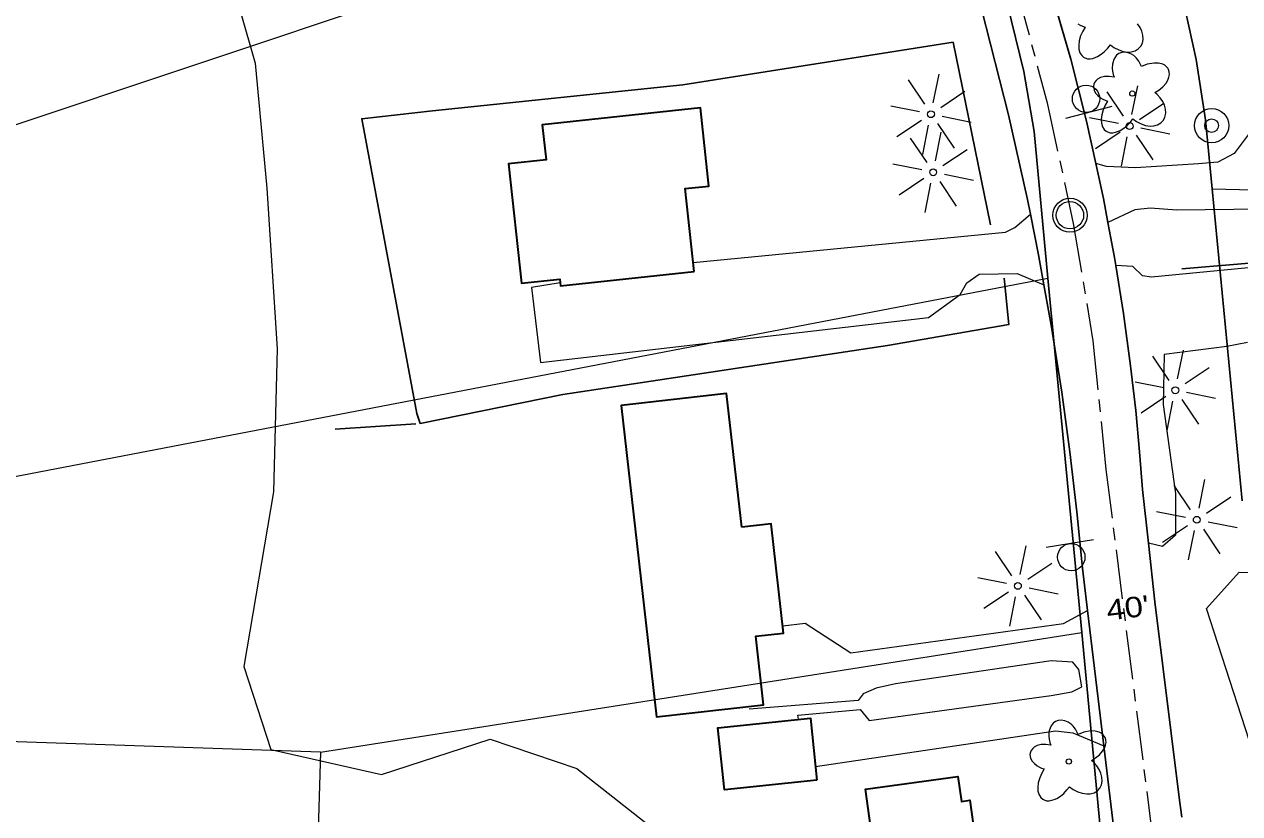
# Model space of a CAD drawing. Extents: x -861682 to -858969, y -1797841 to -1795153.
# Drawn here: x -859508.8 to -859153.4, y -1796143 to -1795912 of the extents above; entities that cross this region are included whole.
import ezdxf

# ---------------------------------------------------------------- set-up
doc = ezdxf.new("R2010")
doc.units = 0
doc.header["$LTSCALE"] = 2.4
doc.linetypes.add('LONG_DASH_SHORT_DASH', pattern=[9.9, 6, -1.2, 1.5, -1.2])
for name, color, linetype, lineweight in [('10', 7, 'Continuous', 25), ('11', 7, 'Continuous', 13), ('12', 7, 'Continuous', 35), ('14', 7, 'Continuous', 25), ('17', 7, 'Continuous', 13), ('18', 7, 'Continuous', 13), ('21', 7, 'Continuous', 13), ('30', 7, 'Continuous', 13), ('31', 7, 'Continuous', 13), ('32', 7, 'LONG_DASH_SHORT_DASH', 13), ('36', 7, 'Continuous', 13), ('42', 7, 'Continuous', 25)]:
    doc.layers.add(name, color=color, linetype=linetype, lineweight=lineweight)
doc.layers.add('43', color=7, linetype='Continuous')

msp = doc.modelspace()

# ---------------------------------------------------------------- linework, layer by layer
at = {"layer": '10'}
for p, q in [((-859180.121, -1796063.829), (-859181.863, -1796048.128)), ((-859197.871, -1796083.551), (-859199.352, -1796071.145)), ((-859197.871, -1796083.551), (-859193.138, -1796123.219))]:
    msp.add_line(p, q, dxfattribs=at)
for points in [[(-859195.488, -1795952.759), (-859198.204, -1795940.389), (-859202.803, -1795922.229), (-859208.876, -1795901.043), (-859216.374, -1795877.989), (-859222.374, -1795861.368), (-859224.152, -1795856.696)], [(-859214.603, -1795967.597), (-859215.462, -1795963.305), (-859220.98, -1795938.568), (-859228.914, -1795907.477), (-859230.246, -1795902.657)], [(-859195.488, -1795952.759), (-859193.242, -1795962.991), (-859191.918, -1795970.065)], [(-859210.647, -1795988.294), (-859212.222, -1795979.514), (-859214.603, -1795967.597)], [(-859191.918, -1795970.065), (-859189.999, -1795980.322), (-859189.628, -1795982.635)], [(-859189.628, -1795982.635), (-859187.383, -1795996.643), (-859185.313, -1796011.931), (-859183.826, -1796025.071), (-859182.696, -1796037.14), (-859181.863, -1796048.128)], [(-859210.647, -1795988.294), (-859208.526, -1796000.123), (-859205.447, -1796019.718), (-859203.055, -1796037.187), (-859200.99, -1796054.697), (-859199.352, -1796071.145)], [(-859180.121, -1796063.829), (-859178.218, -1796080.987), (-859171.015, -1796139.046), (-859170.355, -1796144.002)], [(-859193.138, -1796123.219), (-859185.092, -1796190.648), (-859181.823, -1796229.868)]]:
    msp.add_lwpolyline(points, dxfattribs=at)
at = {"layer": '11'}
for points in [[(-859138.966, -1795909.721), (-859146.102, -1795933.276), (-859149.733, -1795942.803), (-859155.018, -1795949.883), (-859159.831, -1795952.351), (-859165.413, -1795952.878), (-859183.893, -1795954.081), (-859192.373, -1795953.671), (-859195.488, -1795952.759)], [(-859127.758, -1795912.644), (-859137.418, -1795947.471), (-859137.261, -1795952.153), (-859134.574, -1795954.343), (-859128.865, -1795954.666), (-859114.589, -1795953.858), (-859113.648, -1795965.788), (-859171.8, -1795966.396), (-859179.569, -1795965.851), (-859184.024, -1795966.336), (-859191.918, -1795970.065)], [(-859313.252, -1795981.692), (-859221.93, -1795972.849), (-859219.15, -1795971.531), (-859214.603, -1795967.597)], [(-859042.087, -1795984.119), (-859043.027, -1795974.565), (-859116.563, -1795980.029), (-859179.237, -1795986.038), (-859181.848, -1795985.61), (-859184.682, -1795982.919), (-859189.628, -1795982.635)], [(-859352.064, -1795987.667), (-859360.515, -1795989.037), (-859357.825, -1796011.045), (-859244.428, -1795997.858), (-859235.189, -1795991.073), (-859233.172, -1795987.708), (-859229.548, -1795985.138), (-859218.502, -1795984.92), (-859210.647, -1795988.294)], [(-859151.173, -1796005.109), (-859157.125, -1796006.335), (-859175.528, -1796008.666), (-859175.793, -1796023.268), (-859172.173, -1796049.334), (-859172.198, -1796061.561), (-859176.002, -1796064.824), (-859180.121, -1796063.829)], [(-859286.997, -1796088.033), (-859280.413, -1796087.241), (-859267.136, -1796096.004), (-859204.945, -1796087.367), (-859197.871, -1796083.551)], [(-859282.365, -1796115.409), (-859282.571, -1796114.174), (-859264.417, -1796112.532), (-859261.719, -1796115.776), (-859208.529, -1796108.457), (-859202.495, -1796107.393), (-859199.532, -1796105.945), (-859200.435, -1796100.799), (-859202.213, -1796098.695), (-859208.514, -1796098.268), (-859254.084, -1796105.035), (-859259.709, -1796106.333), (-859263.455, -1796107.948), (-859265.008, -1796109.933), (-859296.879, -1796112.451)], [(-859277.429, -1796129.188), (-859207.286, -1796118.788), (-859202.224, -1796119.356), (-859193.138, -1796123.219)]]:
    msp.add_lwpolyline(points, dxfattribs=at)
at = {"layer": '12'}
for points in [[(-859312.961, -1795984.369), (-859315.594, -1795960.115), (-859308.609, -1795959.357), (-859311.092, -1795936.477), (-859357.336, -1795941.495), (-859356.229, -1795951.701), (-859367.188, -1795952.89), (-859363.402, -1795987.785), (-859352.183, -1795986.568), (-859351.962, -1795988.603)], [(-859298.957, -1796059.197), (-859303.418, -1796020.082), (-859334.276, -1796023.601), (-859323.886, -1796114.708), (-859292.647, -1796111.145), (-859294.931, -1796091.119), (-859286.751, -1796090.186), (-859290.397, -1796058.221)], [(-859277.003, -1796133.174), (-859304.082, -1796136.068), (-859306.02, -1796117.937), (-859278.941, -1796115.043)], [(-859256.929, -1796178.303), (-859262.819, -1796135.875), (-859235.792, -1796132.123), (-859234.778, -1796139.424), (-859232.291, -1796139.079), (-859227.418, -1796174.209)]]:
    msp.add_lwpolyline(points, close=True, dxfattribs=at)
at = {"layer": '14'}
msp.add_line((-859394.281, -1796028.926), (-859417.84, -1796030.473), dxfattribs=at)
for points in [[(-859226.25, -1795970.736), (-859237.209, -1795917.304), (-859316.269, -1795929.729), (-859389.434, -1795937.322), (-859410.087, -1795939.667), (-859394.026, -1796025.89), (-859392.998, -1796028.829), (-859351.303, -1796020.368), (-859256.426, -1796005.992), (-859220.871, -1795999.853), (-859222.285, -1795986.35)], [(-859170.328, -1795983.616), (-859043.88, -1795972.952), (-859021.656, -1795971.399), (-859008.81, -1795958.001), (-858992.126, -1795956.088)]]:
    msp.add_lwpolyline(points, dxfattribs=at)
at = {"layer": '17'}
for p, q in [((-859245.489, -1795935.445), (-859250.279, -1795928.317)), ((-859243.029, -1795934.985), (-859241.303, -1795926.585)), ((-859184.936, -1795938.452), (-859183.21, -1795930.052)), ((-859240.829, -1795936.385), (-859233.733, -1795931.645)), ((-859187.396, -1795938.912), (-859192.186, -1795931.784)), ((-859246.989, -1795937.645), (-859255.451, -1795935.971)), ((-859182.736, -1795939.852), (-859175.64, -1795935.112)), ((-859246.449, -1795940.145), (-859253.675, -1795945.001)), ((-859240.389, -1795938.905), (-859231.909, -1795940.629)), ((-859188.896, -1795941.112), (-859197.358, -1795939.438)), ((-859246.069, -1795950.105), (-859244.389, -1795941.505)), ((-859242.375, -1795951.993), (-859240.649, -1795943.593)), ((-859241.729, -1795941.045), (-859236.929, -1795948.259)), ((-859188.356, -1795943.612), (-859195.582, -1795948.468)), ((-859182.296, -1795942.372), (-859173.816, -1795944.096)), ((-859244.835, -1795952.453), (-859249.625, -1795945.325)), ((-859187.976, -1795953.572), (-859186.296, -1795944.972)), ((-859183.636, -1795944.512), (-859178.836, -1795951.726)), ((-859240.175, -1795953.393), (-859233.079, -1795948.653)), ((-859246.335, -1795954.653), (-859254.797, -1795952.979)), ((-859245.795, -1795957.153), (-859253.021, -1795962.009)), ((-859245.415, -1795967.113), (-859243.735, -1795958.513)), ((-859241.075, -1795958.053), (-859236.275, -1795965.267)), ((-859239.735, -1795955.913), (-859231.255, -1795957.637)), ((-859171.586, -1796015.784), (-859169.86, -1796007.384)), ((-859174.046, -1796016.244), (-859178.836, -1796009.116)), ((-859169.386, -1796017.184), (-859162.29, -1796012.444)), ((-859175.546, -1796018.444), (-859184.008, -1796016.77)), ((-859175.006, -1796020.944), (-859182.232, -1796025.8)), ((-859174.626, -1796030.904), (-859172.946, -1796022.304)), ((-859170.286, -1796021.844), (-859165.486, -1796029.058)), ((-859168.946, -1796019.704), (-859160.466, -1796021.428)), ((-859167.758, -1796054.127), (-859172.548, -1796046.999)), ((-859165.298, -1796053.667), (-859163.572, -1796045.267)), ((-859163.098, -1796055.067), (-859156.002, -1796050.327)), ((-859169.258, -1796056.327), (-859177.72, -1796054.653)), ((-859162.658, -1796057.587), (-859154.178, -1796059.311)), ((-859168.718, -1796058.827), (-859175.944, -1796063.683)), ((-859168.338, -1796068.787), (-859166.658, -1796060.187)), ((-859163.998, -1796059.727), (-859159.198, -1796066.941)), ((-859217.599, -1796073.016), (-859215.873, -1796064.616)), ((-859220.059, -1796073.476), (-859224.849, -1796066.348)), ((-859215.399, -1796074.416), (-859208.303, -1796069.676)), ((-859221.559, -1796075.676), (-859230.021, -1796074.002)), ((-859221.019, -1796078.176), (-859228.245, -1796083.032)), ((-859216.299, -1796079.076), (-859211.499, -1796086.29)), ((-859214.959, -1796076.936), (-859206.479, -1796078.66)), ((-859220.639, -1796088.136), (-859218.959, -1796079.536))]:
    msp.add_line(p, q, dxfattribs=at)
for points in [[(-859200.725, -1795911.887), (-859200.027, -1795912.311), (-859199.363, -1795912.599), (-859198.635, -1795912.837), (-859199.319, -1795914.049), (-859199.941, -1795915.417), (-859200.337, -1795916.919), (-859200.471, -1795918.253), (-859200.461, -1795919.343), (-859200.127, -1795920.361), (-859199.605, -1795921.207), (-859199.047, -1795921.643), (-859198.661, -1795921.889), (-859197.927, -1795922.113), (-859197.133, -1795922.125), (-859196.363, -1795922.001), (-859195.703, -1795921.789), (-859194.959, -1795921.467), (-859193.883, -1795920.787), (-859192.921, -1795920.001), (-859191.965, -1795918.983), (-859191.219, -1795918.073)], [(-859191.223, -1795918.063), (-859190.181, -1795918.831), (-859188.775, -1795919.553), (-859187.527, -1795919.959), (-859186.155, -1795920.155), (-859185.137, -1795920.105), (-859183.993, -1795919.815), (-859183.061, -1795919.263), (-859182.321, -1795918.475), (-859181.853, -1795917.517), (-859181.643, -1795916.439), (-859181.747, -1795915.243), (-859182.037, -1795914.071), (-859182.523, -1795913.011), (-859183.245, -1795911.867)], [(-859184.626, -1795939.71), (-859183.584, -1795940.478), (-859182.178, -1795941.2), (-859180.93, -1795941.606), (-859179.558, -1795941.802), (-859178.54, -1795941.752), (-859177.396, -1795941.462), (-859176.464, -1795940.91), (-859175.724, -1795940.122), (-859175.256, -1795939.164), (-859175.046, -1795938.086), (-859175.15, -1795936.89), (-859175.44, -1795935.718), (-859175.926, -1795934.658), (-859176.648, -1795933.514), (-859177.514, -1795932.594), (-859178.196, -1795931.982), (-859177.014, -1795931.266), (-859175.868, -1795930.318), (-859174.948, -1795929.226), (-859174.426, -1795928.37), (-859174.094, -1795927.556), (-859173.948, -1795926.74), (-859173.988, -1795925.978), (-859174.204, -1795925.298), (-859174.462, -1795924.846), (-859174.882, -1795924.372), (-859175.342, -1795924.018), (-859175.908, -1795923.728), (-859177.144, -1795923.4), (-859178.386, -1795923.366), (-859180.432, -1795923.742), (-859182.092, -1795924.38), (-859182.882, -1795922.802), (-859183.536, -1795921.988), (-859183.948, -1795921.586), (-859184.412, -1795921.186), (-859185.014, -1795920.794), (-859186.018, -1795920.362), (-859187.032, -1795920.192), (-859187.92, -1795920.292), (-859188.72, -1795920.626), (-859189.386, -1795921.112), (-859189.946, -1795921.818), (-859190.296, -1795922.574), (-859190.454, -1795923.012), (-859190.622, -1795923.688), (-859190.674, -1795924.85), (-859190.602, -1795925.748), (-859190.39, -1795926.71), (-859190.106, -1795927.516), (-859191.548, -1795927.284), (-859192.906, -1795927.334), (-859194.064, -1795927.62), (-859194.952, -1795928.118), (-859195.392, -1795928.462), (-859195.826, -1795929.028), (-859196.064, -1795929.562), (-859196.188, -1795930.24), (-859195.986, -1795931.344), (-859195.53, -1795932.156), (-859194.906, -1795932.918), (-859194.128, -1795933.534), (-859193.43, -1795933.958), (-859192.766, -1795934.246), (-859192.038, -1795934.484), (-859192.722, -1795935.696), (-859193.344, -1795937.064), (-859193.74, -1795938.566), (-859193.874, -1795939.9), (-859193.864, -1795940.99), (-859193.53, -1795942.008), (-859193.008, -1795942.854), (-859192.45, -1795943.29), (-859192.064, -1795943.536), (-859191.33, -1795943.76), (-859190.536, -1795943.772), (-859189.766, -1795943.648), (-859189.106, -1795943.436), (-859188.362, -1795943.114), (-859187.286, -1795942.434), (-859186.324, -1795941.648), (-859185.368, -1795940.63), (-859184.622, -1795939.72)], [(-859203.173, -1796135.173), (-859202.131, -1796135.941), (-859200.725, -1796136.663), (-859199.477, -1796137.069), (-859198.105, -1796137.265), (-859197.087, -1796137.215), (-859195.943, -1796136.925), (-859195.011, -1796136.373), (-859194.271, -1796135.585), (-859193.803, -1796134.627), (-859193.593, -1796133.549), (-859193.697, -1796132.353), (-859193.987, -1796131.181), (-859194.473, -1796130.121), (-859195.195, -1796128.977), (-859196.061, -1796128.057), (-859196.743, -1796127.445), (-859195.561, -1796126.729), (-859194.415, -1796125.781), (-859193.495, -1796124.689), (-859192.973, -1796123.833), (-859192.641, -1796123.019), (-859192.495, -1796122.203), (-859192.535, -1796121.441), (-859192.751, -1796120.761), (-859193.009, -1796120.309), (-859193.429, -1796119.835), (-859193.889, -1796119.481), (-859194.455, -1796119.191), (-859195.691, -1796118.863), (-859196.933, -1796118.829), (-859198.979, -1796119.205), (-859200.639, -1796119.843), (-859201.429, -1796118.265), (-859202.083, -1796117.451), (-859202.495, -1796117.049), (-859202.959, -1796116.649), (-859203.561, -1796116.257), (-859204.565, -1796115.825), (-859205.579, -1796115.655), (-859206.467, -1796115.755), (-859207.267, -1796116.089), (-859207.933, -1796116.575), (-859208.493, -1796117.281), (-859208.843, -1796118.037), (-859209.001, -1796118.475), (-859209.169, -1796119.151), (-859209.221, -1796120.313), (-859209.149, -1796121.211), (-859208.937, -1796122.173), (-859208.653, -1796122.979), (-859210.095, -1796122.747), (-859211.453, -1796122.797), (-859212.611, -1796123.083), (-859213.499, -1796123.581), (-859213.939, -1796123.925), (-859214.373, -1796124.491), (-859214.611, -1796125.025), (-859214.735, -1796125.703), (-859214.533, -1796126.807), (-859214.077, -1796127.619), (-859213.453, -1796128.381), (-859212.675, -1796128.997), (-859211.977, -1796129.421), (-859211.313, -1796129.709), (-859210.585, -1796129.947), (-859211.269, -1796131.159), (-859211.891, -1796132.527), (-859212.287, -1796134.029), (-859212.421, -1796135.363), (-859212.411, -1796136.453), (-859212.077, -1796137.471), (-859211.555, -1796138.317), (-859210.997, -1796138.753), (-859210.611, -1796138.999), (-859209.877, -1796139.223), (-859209.083, -1796139.235), (-859208.313, -1796139.111), (-859207.653, -1796138.899), (-859206.909, -1796138.577), (-859205.833, -1796137.897), (-859204.871, -1796137.111), (-859203.915, -1796136.093), (-859203.169, -1796135.183)]]:
    msp.add_lwpolyline(points, dxfattribs=at)
for centre, radius in [((-859184.806, -1795932.298), 0.773), ((-859243.689, -1795938.345), 1), ((-859185.596, -1795941.812), 1), ((-859243.035, -1795955.353), 1), ((-859172.246, -1796019.144), 1), ((-859165.958, -1796057.027), 1), ((-859218.259, -1796076.376), 1), ((-859203.353, -1796127.761), 0.773)]:
    msp.add_circle(centre, radius, dxfattribs=at)
at = {"layer": '18'}
for points in [[(-859627.919, -1795735.544), (-859627.176, -1795761.517), (-859594.459, -1795791.233), (-859555.341, -1795807.819), (-859531.043, -1795823.004), (-859501.341, -1795840.813), (-859471.841, -1795856.609), (-859454.844, -1795876.018), (-859441.296, -1795923.448), (-859437.847, -1795959.975), (-859434.854, -1796007.018), (-859435.886, -1796048.843), (-859444.576, -1796099.933), (-859436.676, -1796124.239), (-859404.307, -1796131.553), (-859372.521, -1796121.23), (-859347.215, -1796129.795), (-859321.586, -1796150.045)], [(-859000.584, -1796200.948), (-859030.413, -1796220.763), (-859061.004, -1796234.175), (-859082.06, -1796236.181), (-859097.001, -1796225.145), (-859115.759, -1796225.664), (-859143.622, -1796221.311), (-859148.513, -1796179.853), (-859149.493, -1796125.159), (-859163.095, -1796083.032), (-859153.599, -1796072.325), (-859106.129, -1796073.572), (-859073.857, -1796095.639), (-859070.132, -1796112.997), (-859043.544, -1796120.651), (-859012.341, -1796137.386), (-858996.789, -1796156.325)]]:
    msp.add_lwpolyline(points, dxfattribs=at)
at = {"layer": '21'}
for p, q in [((-859190.807, -1795936.129), (-859204.383, -1795939.564)), ((-859209.953, -1796065), (-859196.126, -1796062.782))]:
    msp.add_line(p, q, dxfattribs=at)
for centre in [(-859198.343, -1795933.849), (-859202.649, -1796067.939)]:
    msp.add_circle(centre, 4, dxfattribs=at)
at = {"layer": '30'}
for p, q in [((-859243.627, -1795852.034), (-859698.943, -1796004.025)), ((-859161.479, -1795960.15), (-859094.584, -1795961.873)), ((-859664.515, -1796073.718), (-859209.471, -1795986.326)), ((-859422.144, -1796125.06), (-859199.551, -1796090.025)), ((-859422.144, -1796125.06), (-859643.077, -1796117.35)), ((-859422.144, -1796125.06), (-859424.402, -1796200.653))]:
    msp.add_line(p, q, dxfattribs=at)
at = {"layer": '31'}
for radius in [5, 2]:
    msp.add_circle((-859161.632, -1795941.691), radius, dxfattribs=at)
at = {"layer": '32'}
msp.add_lwpolyline([(-859608.727, -1795645.905), (-859547.475, -1795663.972), (-859512.218, -1795672.548), (-859448.852, -1795685.888), (-859390.25, -1795702.087), (-859346.418, -1795718.286), (-859312.114, -1795735.914), (-859284.005, -1795754.971), (-859271.617, -1795770.217), (-859251.13, -1795810.238), (-859242.554, -1795833.584), (-859228.738, -1795871.699), (-859218.732, -1795901.238), (-859209.68, -1795935.065), (-859202.057, -1795970.321), (-859196.34, -1796004.625), (-859192.528, -1796042.264), (-859177.759, -1796158.991), (-859172.04, -1796220.929), (-859156.019, -1796407.84)], dxfattribs=at)
at = {"layer": '36'}
for radius in [5, 4]:
    msp.add_circle((-859203.043, -1795967.912), radius, dxfattribs=at)
at = {"layer": '42'}
for p, q in [((-859161.479, -1795960.15), (-859163.411, -1795940.033)), ((-859209.471, -1795986.326), (-859213.511, -1795943.448)), ((-859161.479, -1795960.15), (-859152.648, -1796051.454)), ((-859199.551, -1796090.025), (-859209.471, -1795986.326)), ((-859199.551, -1796090.025), (-859191.962, -1796170.749))]:
    msp.add_line(p, q, dxfattribs=at)
for points in [[(-859163.411, -1795940.033), (-859166.107, -1795922.354), (-859170.428, -1795902.707), (-859177.51, -1795879.161), (-859187.395, -1795854.239), (-859199.37, -1795830.349), (-859213.089, -1795807.924), (-859218.694, -1795799.83)], [(-859243.627, -1795852.034), (-859239.857, -1795858.703), (-859229.069, -1795883.11), (-859221.294, -1795906.355), (-859216.519, -1795925.851), (-859213.511, -1795943.448)]]:
    msp.add_lwpolyline(points, dxfattribs=at)

# ---------------------------------------------------------------- texts
at = {"layer": '43', "width": 1.2}
msp.add_text("40'", height=6, rotation=7.169, dxfattribs=at).set_placement((-859191.998, -1796086.542))

doc.saveas('drawing.dxf')
